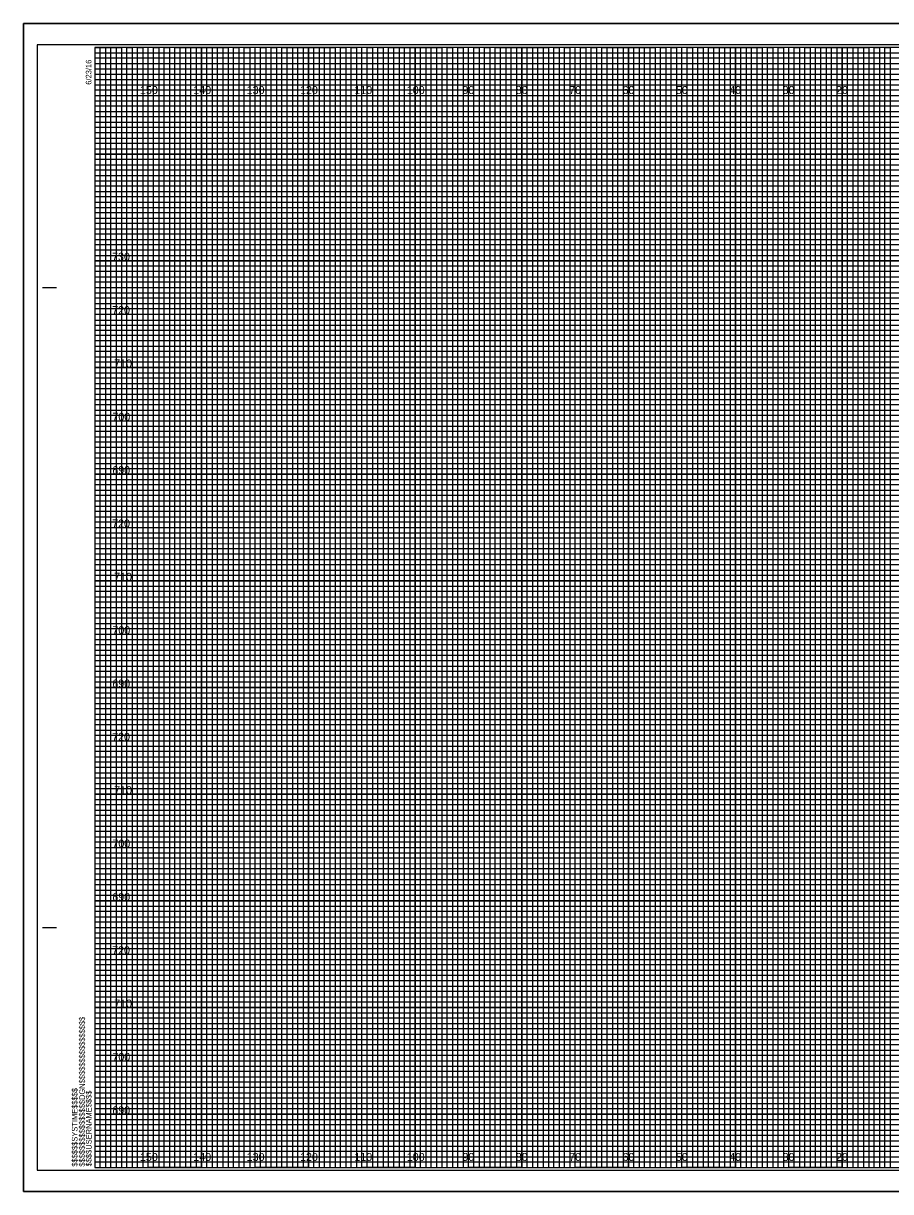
# Model space of a CAD drawing. Extents: x -98 to 717, y -10 to 1974.
# Drawn here: x -13.4 to 149.1, y 435.5 to 654.5 of the extents above; entities that cross this region are included whole.
import ezdxf

# ---------------------------------------------------------------- set-up
doc = ezdxf.new("R2010")
doc.units = 0
for name, color, linetype in [('Default', 7, 'Continuous'), ('Exist XS Center Line Elevation Label', 7, 'Continuous'), ('Prop CMT Conc Surface', 7, 'Continuous'), ('Prop CMT Concrete Structures', 7, 'Continuous'), ('Prop CMT Pvmt Course 1 CG', 7, 'Continuous'), ('Prop CMT Pvmt Course 2', 7, 'Continuous'), ('Prop CMT Pvmt Course 3', 7, 'Continuous'), ('Prop CMT Pvmt Surface', 7, 'Continuous'), ('Prop CMT Subgrade Earthwork', 7, 'Continuous'), ('Prop XS Earthwork Shape', 7, 'Continuous'), ('Prop XS Elevation Labels', 7, 'Continuous'), ('Typical Curb CELL', 7, 'Continuous')]:
    doc.layers.add(name, color=color, linetype=linetype)

msp = doc.modelspace()

# ---------------------------------------------------------------- linework, layer by layer
at = {"layer": 'Default'}
msp.add_lwpolyline([(323.3, 435.5), (-13.4, 435.5), (-13.4, 654.5), (323.3, 654.5)], close=True, dxfattribs=at)
at = {"layer": 'Exist XS Center Line Elevation Label'}
for p, q in [((0, 649), (260, 649)), ((260, 647.98), (0, 647.98)), ((0, 647.98), (0, 647)), ((0, 647), (260, 647)), ((260, 645.89), (0, 645.89)), ((0, 645.89), (0, 644)), ((0, 644), (320, 644))]:
    msp.add_line(p, q, dxfattribs=at)
for points in [[(0, 643), (270, 643), (320, 643), (320, 642), (0, 642)], [(0, 641), (320, 641), (320, 639), (0, 639)], [(0, 638), (320, 638), (320, 637), (0, 636.98)], [(0, 636), (320, 636), (320, 634), (0, 634)], [(0, 633), (320, 633), (320, 632), (0, 632)], [(0, 631), (320, 631), (320, 629), (0, 629)], [(0, 628), (320, 628), (320, 627), (0, 627)], [(0, 626), (320, 626), (320, 624), (0, 624)], [(0, 623), (320, 623), (320, 622), (0, 622)], [(0, 621), (320, 621), (320, 619), (0, 619)], [(0, 618), (320, 618), (320, 617), (0, 617)], [(0, 616), (320, 616), (320, 613.95), (320, 613), (320, 612), (0, 612)], [(0, 614), (320, 614), (320, 613), (0, 613)], [(0, 611), (320, 611), (320, 609), (0, 609.03)], [(0, 609.03), (320, 609), (320, 608), (0, 608)], [(0, 607), (320, 607), (320, 606), (0, 606)], [(0, 604), (320, 604), (320, 603), (0, 603)], [(0, 602), (320, 602), (320, 601), (0, 601)], [(-0.07, 598.89), (320, 598.89), (320, 597.88), (-0.07, 597.88)], [(0, 597), (320, 597), (320, 596), (0, 596)], [(0, 594), (320, 594), (320, 593), (0, 593)], [(0, 592), (320, 592), (320, 591), (0, 591)], [(0, 589), (320, 589), (320, 588), (0, 588)], [(0, 587), (320, 587), (320, 586), (0, 586)], [(0, 584), (320, 584), (320, 583), (0, 583)], [(0, 582), (320, 582), (320, 581), (0, 581)], [(0, 579), (320, 579), (319.99, 577.98), (0, 578)], [(0, 577), (320, 577), (320, 576), (0, 576)], [(0, 574), (320, 574), (320, 573), (0, 573)], [(0, 572), (320, 572), (320, 571), (0, 571)], [(0, 569), (320, 569), (320, 568), (0, 568)], [(0, 567), (320, 567), (320, 566), (0, 566)], [(0, 564), (320, 564), (320, 563), (0, 563)], [(0, 562), (320, 562), (320, 561), (0, 561)], [(0, 559), (320, 559), (320, 558), (0, 558)], [(0, 556.99), (320.07, 556.91), (320, 556), (0, 556)], [(0, 554), (320, 554), (320, 553), (0, 553)], [(0, 552), (320, 552), (320, 551), (0, 551)], [(0, 549), (320, 549), (320, 548), (0, 548)], [(0, 547), (320, 547), (320, 546), (0, 546)], [(0, 544), (320, 544), (320, 543), (0, 543)], [(0, 542), (320, 542), (320, 541), (0, 541)], [(0, 539), (320, 539), (320, 538), (0, 538)], [(0, 537), (320, 537), (320, 536), (0, 536)], [(0, 534), (320, 534), (320, 533), (0, 533)], [(0, 532), (320, 532), (320, 531), (0, 531)], [(0, 529), (320, 529), (320, 528), (0, 528)], [(0, 527), (320, 527), (320, 526), (0, 526)], [(0, 524), (320, 524), (320, 523), (0, 523)], [(0, 522), (320, 522), (320, 521), (0, 521)], [(0, 519), (320, 519), (319.99, 517.98), (0, 518)], [(0, 517), (320, 517), (320, 516), (0, 516)], [(0, 514), (320, 514), (320, 513), (0, 513)], [(0, 512), (320, 512), (320, 511), (0, 511)], [(0, 509), (320, 509), (320, 508), (0, 508)], [(0, 507), (320, 507), (320, 506), (0, 506)], [(0, 504), (320, 504), (320, 503), (0, 503)], [(0, 502), (320, 502), (320, 501), (0, 501)], [(0, 499), (320, 499), (320, 498), (0, 498)], [(0, 496.99), (320.07, 496.91), (320, 496), (0, 496)], [(0, 494), (320, 494), (320, 493), (0, 493)], [(0, 492), (320, 492), (320, 491), (0, 491)], [(0, 489), (320, 489), (320, 488), (0, 488)], [(0, 487), (320, 487), (320, 486), (0, 486)], [(0, 484), (320, 484), (320, 483), (0, 483)], [(0, 482), (320, 482), (320, 481), (0, 481)], [(0, 479), (320, 479), (320, 478), (0, 478)], [(0, 477), (320, 477), (320, 476), (0, 476)], [(0, 474), (320, 474), (320, 473), (0, 473)], [(0, 472), (320, 472), (320, 471), (0, 471)], [(0, 469), (320, 469), (320, 468), (0, 468)], [(0, 467), (320, 467), (320, 466), (0, 466)], [(0, 464), (320, 464), (320, 463), (0, 463)], [(0, 462), (320, 462), (320, 461), (0, 461)], [(0, 459), (320, 459), (320, 458), (0, 458)], [(0, 457), (320, 457), (320, 456), (0, 456)], [(0, 454), (320, 454), (320, 453), (0, 453)], [(0, 452), (320, 452), (320, 451), (0, 451)], [(0, 449), (320, 449), (320, 448), (0, 448)], [(0, 447), (320, 447), (320, 446), (0, 446)], [(0, 444), (320, 444), (320, 443), (0, 443)], [(0, 442), (320, 442), (320, 441), (0, 441)]]:
    msp.add_lwpolyline(points, dxfattribs=at)
at = {"layer": 'Prop CMT Conc Surface'}
for p, q in [((-9.8, 605), (-7.3, 605)), ((-9.7, 605), (-7.2, 605)), ((-9.8, 485), (-7.3, 485)), ((-9.7, 485), (-7.2, 485)), ((0, 440), (0, 440)), ((0, 440), (0, 440)), ((0, 440), (0, 440)), ((0, 440), (0, 440)), ((0, 440), (0, 440)), ((0, 440), (0, 440)), ((0, 440), (0, 440))]:
    msp.add_line(p, q, dxfattribs=at)
msp.add_lwpolyline([(320, 650), (0, 650), (0, 440), (320, 440)], close=True, dxfattribs=at)
at = {"layer": 'Prop CMT Concrete Structures'}
for p, q in [((10, 440), (10, 650)), ((20, 440), (20, 650)), ((30, 440), (30, 650)), ((40, 440), (40, 650)), ((50, 440), (50, 650)), ((60, 440), (60, 650)), ((70, 440), (70, 650)), ((80, 440), (80, 650)), ((90, 440), (90, 650)), ((100, 440), (100, 650)), ((110, 440), (110, 650)), ((120, 440), (120, 650)), ((130, 440), (130, 650)), ((140, 440), (140, 650)), ((0, 640), (320, 640)), ((0, 630), (320, 630)), ((0, 620), (320, 620)), ((0, 610), (320, 610)), ((0, 600), (320, 600)), ((0, 590), (320, 590)), ((0, 580), (320, 580)), ((0, 570), (320, 570)), ((0, 560), (320, 560)), ((0, 550), (320, 550)), ((0, 540), (320, 540)), ((0, 530), (320, 530)), ((0, 520), (320, 520)), ((0, 510), (320, 510)), ((0, 500), (320, 500)), ((0, 490), (320, 490)), ((0, 480), (320, 480)), ((0, 470), (320, 470)), ((0, 460), (320, 460)), ((0, 450), (320, 450))]:
    msp.add_line(p, q, dxfattribs=at)
at = {"layer": 'Prop CMT Pvmt Course 2'}
msp.add_lwpolyline([(-13.4, 435.5), (323.3, 435.5), (323.3, 654.5), (-13.4, 654.5)], close=True, dxfattribs=at)
at = {"layer": 'Prop CMT Pvmt Course 3'}
msp.add_lwpolyline([(-10.8, 439.5), (322.4, 439.5), (322.4, 650.5), (-10.8, 650.5)], close=True, dxfattribs=at)
at = {"layer": 'Prop CMT Pvmt Surface'}
for p, q in [((323.3, 654.5), (-13.4, 654.5)), ((-13.4, 654.5), (-13.4, 435.5)), ((-13.4, 435.5), (323.3, 435.5))]:
    msp.add_line(p, q, dxfattribs=at)
at = {"layer": 'Prop CMT Subgrade Earthwork'}
for points in [[(0, 440), (1, 440), (1, 650), (2, 650), (2, 440)], [(2, 440), (3, 440), (3, 650), (4, 650), (4, 440)], [(5, 440), (6, 440), (6, 650), (7, 650), (7, 440)], [(7, 440), (8, 440), (8, 650), (9, 650), (9, 440)], [(10, 440), (11, 440), (11, 650), (12, 650), (12, 440)], [(12, 440), (13, 440), (13, 650), (14, 650), (14, 440)], [(15, 440), (16, 440), (16, 650), (17, 650), (17, 440)], [(17, 440), (18, 440), (18, 650), (19, 650), (19, 440)], [(20, 440), (21, 440), (21, 650), (22, 650), (22, 440)], [(22, 440), (23, 440), (23, 650), (24, 650), (24, 440)], [(25, 440), (26, 440), (26, 650), (27, 650), (27, 440)], [(27, 440), (28, 440), (28, 650), (29, 650), (29, 440)], [(30, 440), (31, 440), (31, 650), (32, 650), (32, 440)], [(32, 440), (33, 440), (33, 650), (34, 650), (34, 440)], [(35, 440), (36, 440), (36, 650), (37, 650), (37, 440)], [(37, 440), (38, 440), (38, 650), (39, 650), (39, 440)], [(40, 440), (41, 440), (41, 650), (42, 650), (42, 440)], [(42, 440), (43, 440), (43, 650), (44, 650), (44, 440)], [(45, 440), (46, 440), (46, 650), (47, 650), (47, 440)], [(47, 440), (48, 440), (48, 650), (49, 650), (49, 440)], [(50, 440), (51, 440), (51, 650), (52, 650), (52, 440)], [(52, 440), (53, 440), (53, 650), (54, 650), (54, 440)], [(55, 440), (56, 440), (56, 650), (57, 650), (57, 440)], [(57, 440), (58, 440), (58, 650), (59, 650), (59, 440)], [(60, 440), (61, 440), (61, 650), (62, 650), (62, 440)], [(62, 440), (63, 440), (63, 650), (64, 650), (64, 440)], [(65, 440), (66, 440), (66, 650), (67, 650), (67, 440)], [(67, 440), (68, 440), (68, 650), (69, 650), (69, 440)], [(70, 440), (71, 440), (71, 650), (72, 650), (72, 440)], [(72, 440), (73, 440), (73, 650), (74, 650), (74, 440)], [(75, 440), (76, 440), (76, 650), (77, 650), (77, 440)], [(77, 440), (78, 440), (78, 650), (79, 650), (79, 440)], [(80, 440), (81, 440), (81, 650), (82, 650), (82, 440)], [(82, 440), (83, 440), (83, 650), (84, 650), (84, 440)], [(85, 440), (86, 440), (86, 650), (87, 650), (87, 440)], [(87, 440), (88, 440), (88, 650), (89, 650), (89, 440)], [(90, 440), (91, 440), (91, 650), (92, 650), (92, 440)], [(92, 440), (93, 440), (93, 650), (94, 650), (94, 440)], [(95, 440), (96, 440), (96, 650), (97, 650), (97, 440)], [(97, 440), (98, 440), (98, 650), (99, 650), (99, 440)], [(100, 440), (101, 440), (101, 650), (102, 650), (102, 440)], [(102, 440), (103, 440), (103, 650), (104, 650), (104, 440)], [(105, 440), (106, 440), (106, 650), (107, 650), (107, 440)], [(107, 440), (108, 440), (108, 650), (109, 650), (109, 440)], [(110, 440), (111, 440), (111, 650), (112, 650), (112, 440)], [(112, 440), (113, 440), (113, 650), (114, 650), (114, 440)], [(115, 440), (116, 440), (116, 650), (117, 650), (117, 440)], [(117, 440), (118, 440), (118, 650), (119, 650), (119, 440)], [(120, 440), (121, 440), (121, 650), (122, 650), (122, 440)], [(122, 440), (123, 440), (123, 650), (124, 650), (124, 440)], [(125, 440), (126, 440), (126, 650), (127, 650), (127, 440)], [(127, 440), (128, 440), (128, 650), (129, 650), (129, 440)], [(130, 440), (131, 440), (131, 650), (132, 650), (132, 440)], [(132, 440), (133, 440), (133, 650), (134, 650), (134, 440)], [(135, 440), (136, 440), (136, 650), (137, 650), (137, 440)], [(137, 440), (138, 440), (138, 650), (139, 650), (139, 440)], [(140, 440), (141, 440), (141, 650), (142, 650), (142, 440)], [(142, 440), (143, 440), (143, 650), (144, 650), (144, 440)], [(145, 440), (146, 440), (146, 650), (147, 650), (147, 440)], [(147, 440), (148, 440), (148, 650), (149, 650), (149, 440)]]:
    msp.add_lwpolyline(points, dxfattribs=at)
at = {"layer": 'Prop XS Elevation Labels'}
for p, q in [((10, 650), (0, 650)), ((10, 440), (10, 650)), ((30, 650), (20, 650)), ((20, 650), (20, 440)), ((30, 440), (30, 650)), ((50, 650), (40, 650)), ((40, 650), (40, 440)), ((50, 440), (50, 650)), ((70, 650), (60, 650)), ((60, 650), (60, 440)), ((70, 440), (70, 650)), ((90, 650), (80, 650)), ((80, 650), (80, 440)), ((90, 440), (90, 650)), ((110, 650), (100, 650)), ((100, 650), (100, 440)), ((110, 440), (110, 650)), ((130, 650), (120, 650)), ((120, 650), (120, 440)), ((130, 440), (130, 650)), ((150, 650), (140, 650)), ((140, 650), (140, 440)), ((20, 440), (10, 440)), ((40, 440), (30, 440)), ((60, 440), (50, 440)), ((80, 440), (70, 440)), ((100, 440), (90, 440)), ((120, 440), (110, 440)), ((140, 440), (130, 440))]:
    msp.add_line(p, q, dxfattribs=at)
for points in [[(0, 640), (320, 640), (320, 630), (0, 630)], [(0, 620), (320, 620), (320, 610), (0, 610)], [(0, 600), (320, 600), (320, 590), (0, 590)], [(0, 580), (320, 580), (320, 570), (0, 570)], [(0, 560), (320, 560), (320, 550), (0, 550)], [(0, 540), (320, 540), (320, 530), (0, 530)], [(0, 520), (320, 520), (320, 510), (0, 510)], [(0, 500), (320, 500), (320, 490), (0, 490)], [(0, 480), (320, 480), (320, 470), (0, 470)], [(0, 460), (320, 460), (320, 450), (0, 450)]]:
    msp.add_lwpolyline(points, dxfattribs=at)
at = {"layer": 'Typical Curb CELL'}
for points in [[(0, 650), (5, 650), (5, 440), (15, 440), (15, 650), (25, 650), (25, 440), (35, 440), (35, 650), (45, 650), (45, 440), (55, 440), (55, 650), (65, 650), (65, 440), (75, 440), (75, 650), (85, 650), (85, 440), (95, 440), (95, 650), (105, 650), (105, 440), (115, 440), (115, 650), (125, 650), (125, 440), (135, 440), (135, 650), (145, 650), (145, 440), (155, 440)], [(0, 645), (275, 645)], [(0, 625), (320, 625), (320, 635), (0, 635)], [(0, 605), (320, 605), (320, 615), (0, 615)], [(0, 585), (320, 585), (320, 595), (0, 595)], [(0, 565), (320, 565), (320, 575), (0, 575)], [(0, 545), (320, 545), (320, 555), (0, 555)], [(0, 525), (320, 525), (320, 535), (0, 535)], [(0, 505), (320, 505), (320, 515), (0, 515)], [(0, 485), (320, 485), (320, 495), (0, 495)], [(0, 465), (320, 465), (320, 475), (0, 475)], [(0, 445), (320, 445), (320, 455), (0, 455)]]:
    msp.add_lwpolyline(points, dxfattribs=at)

# ---------------------------------------------------------------- texts
at = {"layer": 'Prop CMT Conc Surface'}
for s, p in [('6/23/16', (-0.65, 643)), ('$$$$$$$$$$$$$$$$DGN$$$$$$$$$$$$$$$$', (-1.88, 440.18)), ('$$$$$$SYSTIME$$$$$', (-3.26, 440.18)), ('$$$$USERNAME$$$$', (-0.62, 440.23))]:
    msp.add_text(s, height=1.05, rotation=90, dxfattribs=at).set_placement(p)
at = {"layer": 'Prop CMT Pvmt Course 1 CG'}
for s, p in [('730', (3.22, 610)), ('720', (3.23, 600)), ('710', (3.61, 590)), ('700', (3.28, 580)), ('690', (3.26, 570)), ('720', (3.23, 560)), ('710', (3.61, 550)), ('700', (3.28, 540)), ('690', (3.26, 530)), ('720', (3.23, 520)), ('710', (3.61, 510)), ('700', (3.28, 500)), ('690', (3.26, 490)), ('720', (3.23, 480)), ('710', (3.61, 470)), ('700', (3.28, 460)), ('690', (3.26, 450))]:
    msp.add_text(s, height=1.5, dxfattribs=at).set_placement(p)
at = {"layer": 'Prop XS Earthwork Shape'}
for s, p in [('150', (8.44, 641.25)), ('140', (18.44, 641.25)), ('130', (28.44, 641.25)), ('120', (38.44, 641.25)), ('110', (48.62, 641.25)), ('100', (58.44, 641.25)), ('90', (68.86, 641.25)), ('80', (78.86, 641.25)), ('70', (88.86, 641.25)), ('60', (98.86, 641.25)), ('50', (108.86, 641.25)), ('40', (118.86, 641.25)), ('30', (128.86, 641.25)), ('20', (138.86, 641.25)), ('150', (8.44, 441.25)), ('140', (18.44, 441.25)), ('130', (28.44, 441.25)), ('120', (38.44, 441.25)), ('110', (48.62, 441.25)), ('100', (58.44, 441.25)), ('90', (68.86, 441.25)), ('80', (78.86, 441.25)), ('70', (88.86, 441.25)), ('60', (98.86, 441.25)), ('50', (108.86, 441.25)), ('40', (118.86, 441.25)), ('30', (128.86, 441.25)), ('20', (138.86, 441.25))]:
    msp.add_text(s, height=1.5, dxfattribs=at).set_placement(p)

doc.saveas('drawing.dxf')
